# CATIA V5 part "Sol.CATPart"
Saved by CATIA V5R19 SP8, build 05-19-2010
Part number: Sol
Bounding box of the stored display mesh (mm): x -250 to 250, y -250 to 250, z -40 to 0
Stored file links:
  G:\EU_thinkMotion\CFAO_2010\MMS_groupe3\MMS_groupe3\A reprendre\mmugnier\Systeme_Cric_Y\Systeme_Cric_Y\Sol.CATPart
  C:\Users\matthieu\Desktop\CFAO\Systeme_Cric_Y\Cric_Y.CATProduct
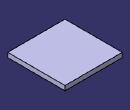
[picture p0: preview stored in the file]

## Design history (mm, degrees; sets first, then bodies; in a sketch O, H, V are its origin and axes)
Set1
  Line1 "Axe 1": linked copy from another document
Set2
  Plane1 "Plan de symétrie": stored without definition
Body1 (main body)
  Sketch1 on Plane1, origin (0, 0, 0), H (0, 1, 0), V (0, 0, 1)
  Sketch2 on xy-plane, origin (0, 0, 0), H (1, 0, 0), V (0, 1, 0)
    line L1 (-250, -250) -> (250, -250)
    line L2 (250, -250) -> (250, 250)
    line L3 (250, 250) -> (-250, 250)
    line L4 (-250, 250) -> (-250, -250)
    reference projected line E1 (-100, 0) -> (100, 0) from Line1
    reference intersected line E2 through (0, 0) direction (0, 1) from yz-plane
    length L2 = 500
    length L3 = 500
    distance L3 E1 = 250
    distance L2 E2 = 250
    horizontal: L1 H, L3 H
    vertical: L2 V, L4 V
  Pad1: profile Sketch2, direction (0, 0, -1), length 40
